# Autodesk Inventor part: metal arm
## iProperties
Author: Rich
Shininess: 20.0
PropertySet Name: _Private Model Information
Created: 2001-04
Part Number: metal arm
Document SubType Name: Sheet Metal
Designer: Rich
Control State: 0
Master: False
Checked Out: False
PropertySet Name: Design Tracking Control
Density: 0.0
Volumn: 0.0
Area: 0.0
PropertySet Name: Model Information
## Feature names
1. Extrusion1
2. Cut1
3. Hole1
4. Hole2
